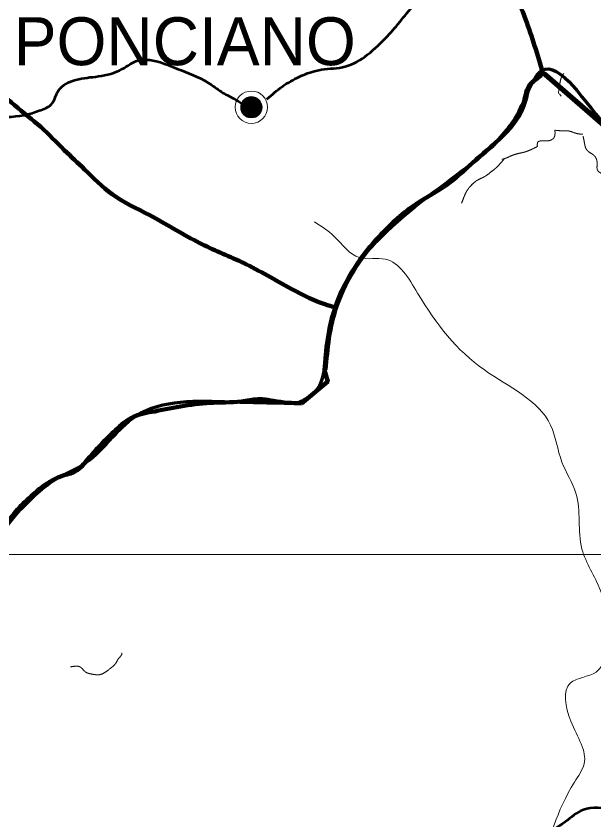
# Model space of a CAD drawing. Extents: x 512883 to 1063249, y 8784064 to 9081064.
# Drawn here: x 730709 to 748785, y 8884279 to 8909438 of the extents above; entities that cross this region are included whole.
import ezdxf

# ---------------------------------------------------------------- set-up
doc = ezdxf.new("R2010")
doc.units = 0
doc.header["$LTSCALE"] = 600
doc.linetypes.add('DOT_DASHED', pattern=[7.7, 5, -1.2, 0.3, -1.2])
for name, color, linetype, lineweight in [('1', 7, 'Continuous', 25), ('10', 7, 'Continuous', 53), ('13', 7, 'Continuous', 90), ('4', 7, 'Continuous', 13), ('5', 7, 'Continuous', 13), ('9', 7, 'Continuous', 70)]:
    doc.layers.add(name, color=color, linetype=linetype, lineweight=lineweight)

msp = doc.modelspace()

# ---------------------------------------------------------------- linework, layer by layer
at = {"layer": '1', "lineweight": 13}
msp.add_line((581090.6, 8892594.3), (934660.9, 8892579.8), dxfattribs=at)
at = {"layer": '10'}
for points in [[(738555.6, 8906838.9), (739048.7, 8907238.7), (739568.3, 8907538.7), (740267.9, 8907763.6), (741007.4, 8907857.4), (741707, 8908232.4), (742326.6, 8908813.6), (742766.3, 8909319.8), (743725.7, 8910369.8), (743857.3, 8910469.4)], [(728825.3, 8905506.4), (729035.2, 8905677.3), (729607.2, 8906173.3), (730163.8, 8906266.2), (731210.7, 8906400.6), (731430.3, 8906478), (731813.3, 8906679.5), (732038, 8907108.3), (732579.3, 8907444.1), (733284.1, 8907552.6), (734034.8, 8907785), (734519.9, 8908048.5), (734933.6, 8908058.8), (735750.6, 8907790.2), (736715.8, 8907351.1), (737134.6, 8907067), (737512.5, 8906855.2), (737772.9, 8906705.3)], [(755690.2, 8888084), (752119.9, 8885734.8), (752219, 8885133.7), (752040.6, 8884432.4), (750792.3, 8884272.1), (750079, 8884512.5), (749385.4, 8884612.7), (748454.1, 8884592.7), (747879.5, 8884211.9), (746651, 8883370.3), (746016.9, 8882528.7), (745382.8, 8881446.7), (744867.7, 8880645.1)]]:
    msp.add_spline(points, degree=3, dxfattribs=at)
at = {"layer": '13'}
msp.add_line((747183, 8907663.5), (751360.9, 8904022.7), dxfattribs=at)
at = {"layer": '13', "lineweight": 25}
msp.add_line((747274.5, 8907680.2), (751452.5, 8904039.4), dxfattribs=at)
at = {"layer": '13'}
msp.add_lwpolyline([(740352, 8898350.5), (740456.5, 8898005.6), (739641.8, 8897315.8)], dxfattribs=at)
for points in [[(731978.6, 8923288.5), (731414.5, 8922814.4), (730600.5, 8922061.6), (730145.5, 8921404.3), (729937.2, 8920644.5), (729637.8, 8919665.5), (729505.7, 8918554.4), (729120, 8917699), (728299.2, 8917099.6), (727420.7, 8916887.6), (726854.1, 8916471), (726595, 8915945.4), (726494.7, 8915479.3), (726726.5, 8914806.3), (726750.4, 8914269.8), (726694, 8913722.8), (726676.5, 8913209.7), (726820.4, 8912698.7), (727143.6, 8911787.2), (727604.4, 8910956.4), (728002.6, 8910170.4), (728573.4, 8909137.3), (729038.5, 8908210.8), (729883.7, 8907358.3), (730662.1, 8906646.5), (731479.3, 8905968.6), (732218, 8905241.9), (732850.2, 8904640.9), (733712.2, 8903862.9), (734891.9, 8903203.9), (736361.3, 8902380.6), (737671.2, 8901784.3)], [(747183, 8907663.5), (746645.8, 8909337.4), (745819.5, 8911122.2), (745111.8, 8912513.1), (744573.3, 8914135.4)], [(740352, 8898350.5), (740456.5, 8899327.8), (740707.2, 8900362.6), (741292.1, 8901550.7), (742106.8, 8902585.5), (743234.8, 8903562.8), (744070.4, 8904080.1), (744989.6, 8904846.6), (745887.8, 8905651.5), (746598.1, 8906762.9), (746786.1, 8907299.4), (747099.4, 8907567.7), (747183, 8907663.5)], [(737671.2, 8901784.3), (737824, 8901710.6), (739312.9, 8900904.2), (740486.6, 8900379.3), (740694.6, 8900324.9)], [(732462.4, 8895131.9), (732560.2, 8895188.7), (732957.1, 8895572), (733437.5, 8896108.5), (733813.6, 8896472.6), (734377.6, 8896894.2), (735046.1, 8897066.7), (735965.2, 8897239.1), (736884.3, 8897334.9), (737887.1, 8897392.4), (738409.3, 8897449.9), (738764.4, 8897392.4), (739641.8, 8897315.8)], [(729681.8, 8891142.3), (729656.5, 8891567), (729949, 8892601.8), (730450.3, 8893598.2), (731369.5, 8894575.5), (732017, 8894997.1), (732477.9, 8895138.8)]]:
    msp.add_spline(points, degree=3, dxfattribs=at)
at = {"layer": '13', "lineweight": 25}
for points in [[(740443.6, 8898367.2), (740548, 8899344.5), (740798.7, 8900379.3), (741383.6, 8901567.4), (742198.3, 8902602.2), (743326.4, 8903579.5), (744162, 8904096.8), (745081.1, 8904863.3), (745979.3, 8905668.2), (746689.6, 8906779.6), (746877.6, 8907316.2), (747191, 8907584.4), (747274.5, 8907680.2)], [(732554, 8895148.6), (732651.7, 8895205.4), (733048.6, 8895588.7), (733529.1, 8896125.2), (733905.1, 8896489.3), (734469.1, 8896910.9), (735137.6, 8897083.4), (736056.7, 8897255.8), (736975.9, 8897351.6), (737978.6, 8897409.1), (738500.8, 8897466.6), (738856, 8897409.1), (739733.3, 8897332.5)], [(729773.3, 8891159), (729748, 8891583.7), (730040.5, 8892618.5), (730541.8, 8893614.9), (731461, 8894592.2), (732108.6, 8895013.8), (732569.4, 8895155.5)]]:
    msp.add_spline(points, degree=3, dxfattribs=at)
at = {"layer": '4', "linetype": 'DOT_DASHED'}
msp.add_line((747709.7, 8907001.7), (747764.6, 8906925.9), dxfattribs=at)
for points in [[(747676, 8907019.3), (747744, 8907444.4), (747795.2, 8907577.7), (747846.4, 8907644.4)], [(747015.8, 8905355.4), (747027.3, 8905485.9), (747339.6, 8905532), (747539.2, 8905639.7), (747564.8, 8905865.3)], [(748435.5, 8905738.9), (748225.3, 8905767.9), (748005.1, 8905839.7), (747846.4, 8905844.8), (747564.8, 8905865.3)], [(748444.5, 8905677), (748481.2, 8905506.4), (748568.3, 8905239.8), (748803.8, 8905060.4), (748885.7, 8904834.8), (748890.8, 8904629.7), (749208.2, 8904440), (749438.6, 8904245.2), (749446.7, 8904119.4)], [(747015.8, 8905355.4), (746587, 8905173.2), (746361.8, 8905121.9), (746121.2, 8905029.6), (745998.3, 8904978.3), (745911.3, 8904952.7)], [(744957.9, 8904150.7), (745148.7, 8904306.9), (745351.3, 8904405.7), (745554.1, 8904551.4), (745706.1, 8904671), (745853, 8904821.8), (745984.3, 8904974.2)], [(744972.7, 8904162.2), (744824.3, 8903989.6), (744702.7, 8903729.5), (744641.9, 8903578.7)], [(732416, 8889070.2), (732736.8, 8889052.8), (732865.2, 8888920.9), (733070.6, 8888844.8), (733342.8, 8888829.6), (733620, 8888991.9), (733825.4, 8889179.6), (733923, 8889341.9), (734020.5, 8889489.1), (734020.5, 8889504.3)]]:
    msp.add_spline(points, degree=3, dxfattribs=at)
at = {"layer": '4'}
msp.add_spline([(744501.9, 8869598.5), (744470, 8870556.5), (743738.4, 8872229.9), (744063.6, 8873152.6), (743349.9, 8874434.9), (743618.1, 8875934.2), (744918.6, 8879583.7), (745542.8, 8880277.2), (747016.9, 8882711.3), (748172.5, 8885457), (748475.8, 8886030.2), (748062.7, 8887371.4), (748049, 8888564.8), (748851.5, 8888906.8), (749198.3, 8890137.9), (748985.3, 8891477.2), (748411.7, 8892758.2), (748220.9, 8894508.7), (747785.8, 8895479.8), (747431.7, 8896635.3), (745359.3, 8898362.7), (743270.6, 8900769.2), (742255.5, 8901828.1), (741455.1, 8901876.9), (740658, 8902542.9), (740040, 8903001.4)], degree=3, dxfattribs=at)
at = {"layer": '5'}
for p, q in [((737848.3, 8906833.7), (738289.9, 8906833.7)), ((737887.9, 8906863.7), (738250.3, 8906863.7)), ((737945.2, 8906893.7), (738193, 8906893.7)), ((737736.7, 8906593.7), (738401.5, 8906593.7)), ((737738.8, 8906623.7), (738399.4, 8906623.7)), ((737743.6, 8906653.7), (738394.6, 8906653.7)), ((737751.7, 8906683.7), (738386.5, 8906683.7)), ((737762.5, 8906713.7), (738375.7, 8906714)), ((737776.9, 8906743.7), (738361.6, 8906743.7)), ((737795.2, 8906773.7), (738343.3, 8906773.7)), ((737819.2, 8906803.7), (738319.6, 8906803.7)), ((737737.3, 8906563.7), (738401.2, 8906563.7)), ((737740.3, 8906533.7), (738397.9, 8906533.7)), ((737746.3, 8906503.7), (738391.9, 8906503.7)), ((737755.3, 8906473.7), (738382.9, 8906473.7)), ((737767.9, 8906443.7), (738370.6, 8906444)), ((737783.8, 8906413.7), (738354.4, 8906413.7)), ((737804.5, 8906383.7), (738334, 8906384)), ((737829.7, 8906353.4), (738308.8, 8906353.7)), ((737863, 8906323.7), (738275.2, 8906323.7)), ((737908, 8906293.7), (738230.2, 8906293.7)), ((737981.8, 8906263.7), (738156.1, 8906263.7))]:
    msp.add_line(p, q, dxfattribs=at)
for radius in [506.1, 332.9]:
    msp.add_circle((738069.2, 8906584.7), radius, dxfattribs=at)
at = {"layer": '9'}
for points in [[(739491.5, 8897319.2), (740049.1, 8897660.7), (740437.9, 8899153.6), (741034.8, 8901113.8), (743561.4, 8903764.3), (745471.9, 8905265.6), (746442.1, 8906464.9), (747159.6, 8907736.3), (749272, 8905843.1), (750962.4, 8904370)], [(729699, 8891025.9), (729748.4, 8892070.1), (730861.6, 8894002.8), (732096, 8895026.1), (732763.6, 8895371), (734460.9, 8896926.1), (737423.4, 8897366.9), (739641.8, 8897315.8)]]:
    msp.add_spline(points, degree=3, dxfattribs=at)

# ---------------------------------------------------------------- texts
at = {"layer": '5'}
msp.add_text('PONCIANO', height=1500, dxfattribs=at).set_placement((730636.6, 8907899.8))

doc.saveas('drawing.dxf')
